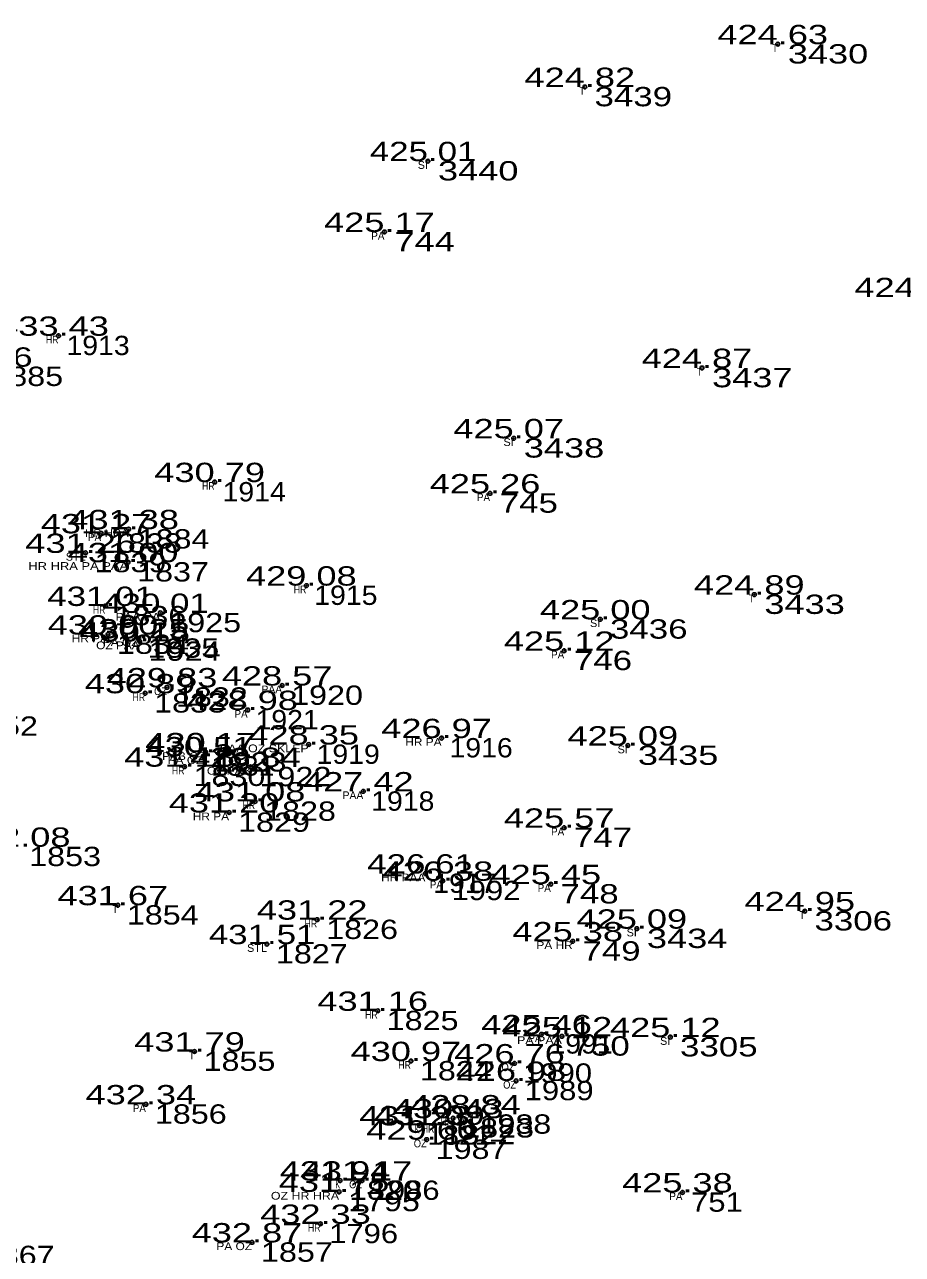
# Model space of a CAD drawing. Extents: x -639390 to -639074, y -1138747 to -1138358.
# Drawn here: x -639298.45 to -639264.37, y -1138517.05 to -1138469.3 of the extents above; entities that cross this region are included whole.
import ezdxf
from ezdxf.enums import TextEntityAlignment as Align

# ---------------------------------------------------------------- set-up
doc = ezdxf.new("R2010")
doc.units = 0
doc.header["$LTSCALE"] = 0.3
doc.header["$PDMODE"] = 32
doc.header["$PDSIZE"] = 0.15
for name, color, linetype in [('11', 7, 'Continuous'), ('12', 7, 'Continuous'), ('13', 7, 'Continuous'), ('57', 7, 'Continuous')]:
    doc.layers.add(name, color=color, linetype=linetype)

msp = doc.modelspace()

# ---------------------------------------------------------------- linework, layer by layer
at = {"layer": '11'}
for p in [(-639269.21, -1138470.06), (-639276.7, -1138471.72), (-639282.79, -1138474.6), (-639284.48, -1138477.35), (-639297.13, -1138481.38), (-639272.15, -1138482.63), (-639279.46, -1138485.36), (-639291.07, -1138487.06), (-639280.38, -1138487.5), (-639294.41, -1138488.89), (-639295.48, -1138489.05), (-639296.08, -1138489.81), (-639294.43, -1138490.17), (-639287.51, -1138491.08), (-639295.31, -1138491.87), (-639270.12, -1138491.43), (-639293.18, -1138492.14), (-639276.1, -1138492.39), (-639295.21, -1138492.98), (-639294.03, -1138493.13), (-639293.98, -1138493.25), (-639277.5, -1138493.61), (-639292.92, -1138495.03), (-639288.45, -1138494.96), (-639293.77, -1138495.26), (-639289.79, -1138495.91), (-639282.26, -1138497), (-639291.42, -1138497.55), (-639287.42, -1138497.25), (-639275.03, -1138497.29), (-639291.51, -1138497.71), (-639292.24, -1138498.11), (-639289.68, -1138498.12), (-639289.5, -1138499.46), (-639285.3, -1138499.07), (-639290.51, -1138499.89), (-639277.5, -1138500.48), (-639282.89, -1138502.26), (-639282.21, -1138502.54), (-639278.02, -1138502.67), (-639294.83, -1138503.49), (-639268.16, -1138503.72), (-639287.09, -1138504.05), (-639274.68, -1138504.4), (-639289.04, -1138505), (-639277.17, -1138504.89), (-639284.74, -1138507.59), (-639278.38, -1138508.5), (-639277.59, -1138508.58), (-639273.38, -1138508.61), (-639291.85, -1138509.17), (-639283.45, -1138509.54), (-639279.43, -1138509.63), (-639279.37, -1138510.31), (-639293.74, -1138511.22), (-639281.81, -1138511.76), (-639281.14, -1138511.61), (-639283.12, -1138512.04), (-639282.54, -1138512.02), (-639282.84, -1138512.59), (-639286.2, -1138514.18), (-639285.35, -1138514.18), (-639286.24, -1138514.62), (-639272.91, -1138514.64), (-639286.96, -1138515.86), (-639289.62, -1138516.58)]:
    msp.add_point(p, dxfattribs=at)

# ---------------------------------------------------------------- texts
at = {"layer": '12'}
for s, width, p in [('424.63 ', 1.4, (-639269.21, -1138470.06)), ('424.82 ', 1.4, (-639276.7, -1138471.72)), ('425.01 ', 1.35, (-639282.789, -1138474.6)), ('425.17 ', 1.4, (-639284.48, -1138477.35)), ('424.62 ', 1.4, (-639263.89, -1138479.88)), ('433.43 ', 1.4, (-639297.13, -1138481.38)), ('434.36 ', 1.4, (-639300.089, -1138482.58)), ('424.87 ', 1.4, (-639272.15, -1138482.63)), ('425.07 ', 1.4, (-639279.46, -1138485.36)), ('430.79 ', 1.4, (-639291.07, -1138487.06)), ('425.26 ', 1.4, (-639280.379, -1138487.5)), ('431.27 ', 1.4, (-639295.48, -1138489.05)), ('431.38 ', 1.4, (-639294.41, -1138488.89)), ('431.26 ', 1.4, (-639296.079, -1138489.81)), ('431.00 ', 1.4, (-639294.43, -1138490.17)), ('429.08 ', 1.4, (-639287.51, -1138491.08)), ('424.89 ', 1.4, (-639270.12, -1138491.43)), ('431.01 ', 1.35, (-639295.309, -1138491.87)), ('430.01 ', 1.35, (-639293.179, -1138492.14)), ('425.00 ', 1.4, (-639276.1, -1138492.39)), ('430.90 ', 1.4, (-639295.21, -1138492.98)), ('430.25 ', 1.4, (-639294.03, -1138493.13)), ('430.18 ', 1.4, (-639293.98, -1138493.25)), ('425.12 ', 1.4, (-639277.5, -1138493.61)), ('428.57 ', 1.4, (-639288.45, -1138494.96)), ('430.89 ', 1.4, (-639293.77, -1138495.26)), ('429.83 ', 1.4, (-639292.92, -1138495.03)), ('428.98 ', 1.4, (-639289.79, -1138495.91)), ('428.35 ', 1.4, (-639287.42, -1138497.25)), ('426.97 ', 1.4, (-639282.26, -1138497)), ('425.09 ', 1.4, (-639275.03, -1138497.29)), ('430.51 ', 1.35, (-639291.509, -1138497.71)), ('430.17 ', 1.4, (-639291.42, -1138497.55)), ('431.18 ', 1.4, (-639292.24, -1138498.11)), ('429.84 ', 1.4, (-639289.68, -1138498.12)), ('427.42 ', 1.4, (-639285.3, -1138499.07)), ('431.08 ', 1.4, (-639289.5, -1138499.46)), ('431.20 ', 1.4, (-639290.51, -1138499.89)), ('425.57 ', 1.4, (-639277.5, -1138500.48)), ('432.08 ', 1.4, (-639298.62, -1138501.22)), ('426.61 ', 1.35, (-639282.889, -1138502.26)), ('426.38 ', 1.4, (-639282.21, -1138502.54)), ('425.45 ', 1.4, (-639278.02, -1138502.67)), ('431.67 ', 1.4, (-639294.83, -1138503.49)), ('424.95 ', 1.4, (-639268.16, -1138503.72)), ('431.22 ', 1.4, (-639287.09, -1138504.05)), ('425.09 ', 1.4, (-639274.68, -1138504.4)), ('425.38 ', 1.4, (-639277.17, -1138504.89)), ('431.51 ', 1.35, (-639289.039, -1138505)), ('431.16 ', 1.4, (-639284.739, -1138507.59)), ('425.46 ', 1.4, (-639278.379, -1138508.5)), ('425.12 ', 1.4, (-639277.59, -1138508.58)), ('425.12 ', 1.4, (-639273.38, -1138508.61)), ('431.79 ', 1.4, (-639291.85, -1138509.17)), ('430.97 ', 1.4, (-639283.45, -1138509.54)), ('426.76 ', 1.4, (-639279.429, -1138509.63)), ('426.98 ', 1.4, (-639279.37, -1138510.31)), ('432.34 ', 1.4, (-639293.74, -1138511.22)), ('428.84 ', 1.4, (-639281.14, -1138511.61)), ('431.23 ', 1.4, (-639283.12, -1138512.04)), ('431.09 ', 1.4, (-639282.54, -1138512.02)), ('430.43 ', 1.4, (-639281.81, -1138511.76)), ('429.60 ', 1.4, (-639282.84, -1138512.59)), ('431.94 ', 1.4, (-639286.2, -1138514.18)), ('431.17 ', 1.4, (-639285.35, -1138514.18)), ('431.75 ', 1.4, (-639286.24, -1138514.62)), ('425.38 ', 1.4, (-639272.91, -1138514.64)), ('432.33 ', 1.4, (-639286.96, -1138515.86)), ('432.87 ', 1.4, (-639289.62, -1138516.58))]:
    msp.add_text(s, height=0.75, dxfattribs=dict(at, width=width)).set_placement(p, align=Align.CENTER)
at = {"layer": '13'}
for s, width, p in [(' 3430', 1.4, (-639269.21, -1138470.81)), (' 3439', 1.35, (-639276.7, -1138472.47)), (' 3440', 1.4, (-639282.79, -1138475.35)), (' 744', 1.4, (-639284.48, -1138478.1)), (' 1913', 1.1, (-639297.13, -1138482.13)), (' 1885', 1.25, (-639300.09, -1138483.33)), (' 3437', 1.4, (-639272.15, -1138483.38)), (' 3438', 1.4, (-639279.46, -1138486.11)), (' 1914', 1.1, (-639291.07, -1138487.81)), (' 745', 1.35, (-639280.38, -1138488.25)), (' 1884', 1.25, (-639294.41, -1138489.64)), (' 1838', 1.25, (-639295.48, -1138489.8)), (' 1839', 1.25, (-639296.08, -1138490.56)), (' 1837', 1.25, (-639294.43, -1138490.92)), (' 1915', 1.1, (-639287.51, -1138491.83)), (' 3433', 1.4, (-639270.12, -1138492.18)), (' 1836', 1.25, (-639295.31, -1138492.62)), (' 1925', 1.25, (-639293.18, -1138492.89)), (' 3436', 1.35, (-639276.1, -1138493.14)), (' 1834', 1.25, (-639295.21, -1138493.73)), (' 1835', 1.25, (-639294.03, -1138493.88)), (' 1924', 1.25, (-639293.98, -1138494)), (' 746', 1.35, (-639277.5, -1138494.36)), (' 1832', 1.25, (-639292.92, -1138495.78)), (' 1920', 1.25, (-639288.45, -1138495.71)), (' 1833', 1.25, (-639293.77, -1138496.01)), (' 1921', 1.1, (-639289.79, -1138496.66)), (' 1852', 1.25, (-639301.07, -1138496.91)), (' 1916', 1.1, (-639282.26, -1138497.75)), (' 1923', 1.25, (-639291.42, -1138498.3)), (' 1919', 1.1, (-639287.42, -1138498)), (' 3435', 1.4, (-639275.03, -1138498.04)), (' 1831', 1.1, (-639291.51, -1138498.46)), (' 1830', 1.25, (-639292.24, -1138498.86)), (' 1922', 1.25, (-639289.68, -1138498.87)), (' 1828', 1.25, (-639289.5, -1138500.21)), (' 1918', 1.1, (-639285.3, -1138499.82)), (' 1829', 1.25, (-639290.51, -1138500.64)), (' 747', 1.35, (-639277.5, -1138501.23)), (' 1853', 1.25, (-639298.62, -1138501.97)), (' 1917', 1.1, (-639282.89, -1138503.01)), (' 1992', 1.2, (-639282.21, -1138503.29)), (' 748', 1.35, (-639278.02, -1138503.42)), (' 1854', 1.25, (-639294.83, -1138504.24)), (' 3306', 1.35, (-639268.16, -1138504.47)), (' 1826', 1.25, (-639287.09, -1138504.8)), (' 3434', 1.4, (-639274.68, -1138505.15)), (' 1827', 1.25, (-639289.04, -1138505.75)), (' 749', 1.35, (-639277.17, -1138505.64)), (' 1825', 1.25, (-639284.74, -1138508.34)), (' 1991', 1.1, (-639278.38, -1138509.25)), (' 750', 1.35, (-639277.59, -1138509.33)), (' 3305', 1.35, (-639273.38, -1138509.36)), (' 1855', 1.25, (-639291.85, -1138509.92)), (' 1824', 1.25, (-639283.45, -1138510.29)), (' 1990', 1.2, (-639279.43, -1138510.38)), (' 1989', 1.2, (-639279.37, -1138511.06)), (' 1856', 1.25, (-639293.74, -1138511.97)), (' 1823', 1.25, (-639281.81, -1138512.51)), (' 1988', 1.25, (-639281.14, -1138512.36)), (' 1821', 1.1, (-639283.12, -1138512.79)), (' 1822', 1.25, (-639282.54, -1138512.77)), (' 1987', 1.25, (-639282.84, -1138513.34)), (' 1820', 1.25, (-639286.2, -1138514.93)), (' 1986', 1.2, (-639285.35, -1138514.93)), (' 1795', 1.25, (-639286.24, -1138515.37)), (' 751', 1.2, (-639272.91, -1138515.39)), (' 1796', 1.2, (-639286.96, -1138516.61)), (' 1857', 1.25, (-639289.62, -1138517.33)), (' 1867', 1.25, (-639300.42, -1138517.46))]:
    msp.add_text(s, height=0.75, dxfattribs=dict(at, width=width)).set_placement(p)
at = {"layer": '57'}
for s, width, p in [('T', 0.85, (-639269.21, -1138470.36)), ('T', 0.85, (-639276.7, -1138472.02)), ('SI', 1.05, (-639282.79, -1138474.9)), ('PA', 0.95, (-639284.48, -1138477.65)), ('HR', 0.85, (-639297.129, -1138481.68)), ('T', 0.85, (-639272.15, -1138482.93)), ('SI', 1.05, (-639279.46, -1138485.66)), ('HR', 0.85, (-639291.069, -1138487.36)), ('PA', 0.95, (-639280.38, -1138487.8)), ('HR HRA', 1.1, (-639294.41, -1138489.19)), ('PA', 0.95, (-639295.48, -1138489.35)), ('STL', 1.05, (-639296.079, -1138490.11)), ('HR HRA PA PAA', 1.25, (-639294.43, -1138490.47)), ('HR', 0.85, (-639287.509, -1138491.38)), ('T', 0.85, (-639270.12, -1138491.73)), ('HR', 0.85, (-639295.309, -1138492.17)), ('PAA PA', 1.2, (-639293.18, -1138492.44)), ('SI', 1.05, (-639276.1, -1138492.69)), ('HR PA', 1.15, (-639295.21, -1138493.28)), ('OZ PAA', 1.15, (-639293.98, -1138493.55)), ('PA OZ', 1.15, (-639294.029, -1138493.43)), ('PA', 0.95, (-639277.5, -1138493.91)), ('OZ', 0.9, (-639292.919, -1138495.33)), ('HR', 0.85, (-639293.769, -1138495.56)), ('PA', 0.95, (-639289.79, -1138496.21)), ('HR PA', 1.15, (-639282.26, -1138497.3)), ('PAB OZ', 1.15, (-639291.419, -1138497.85)), ('PAA OZ SKLEP', 1.2, (-639287.419, -1138497.55)), ('SI', 1.05, (-639275.03, -1138497.59)), ('PA OZ', 1.15, (-639291.509, -1138498.01)), ('HR', 0.85, (-639292.239, -1138498.41)), ('OZ PAB', 1.15, (-639289.679, -1138498.42)), ('HR PA', 1.15, (-639290.51, -1138500.19)), ('HR', 0.85, (-639289.499, -1138499.76)), ('PA', 0.95, (-639277.5, -1138500.78)), ('HR PAA', 1.15, (-639282.89, -1138502.56)), ('PA', 0.95, (-639282.21, -1138502.84)), ('PA', 0.95, (-639278.02, -1138502.97)), ('T', 0.85, (-639294.83, -1138503.79)), ('T', 0.85, (-639268.16, -1138504.02)), ('HR', 0.85, (-639287.089, -1138504.35)), ('SI', 1.05, (-639274.68, -1138504.7)), ('STL', 1.05, (-639289.039, -1138505.3)), ('PA HR', 1.15, (-639277.169, -1138505.19)), ('HR', 0.85, (-639284.739, -1138507.89)), ('PA', 0.95, (-639278.38, -1138508.8)), ('PA PAA', 1.2, (-639277.59, -1138508.88)), ('SI', 1.05, (-639273.38, -1138508.91)), ('T', 0.85, (-639291.85, -1138509.47)), ('HR', 0.85, (-639283.449, -1138509.84)), ('OZ', 0.9, (-639279.429, -1138509.93)), ('OZ', 0.9, (-639279.369, -1138510.61)), ('PA', 0.95, (-639293.74, -1138511.52)), ('HR', 0.85, (-639281.809, -1138512.06)), ('OZ', 0.9, (-639281.139, -1138511.91)), ('K', 0.65, (-639283.119, -1138512.34)), ('HR', 0.85, (-639282.539, -1138512.32)), ('OZ', 0.9, (-639282.839, -1138512.89)), ('K', 0.65, (-639286.199, -1138514.48)), ('OZ', 0.9, (-639285.349, -1138514.48)), ('OZ HR HRA', 1.2, (-639286.24, -1138514.92)), ('PA', 0.95, (-639272.91, -1138514.94)), ('HR', 0.85, (-639286.959, -1138516.16)), ('PA OZ', 1.15, (-639289.619, -1138516.88))]:
    msp.add_text(s, height=0.3, dxfattribs=dict(at, width=width)).set_placement(p, align=Align.RIGHT)
for p in [(-639288.45, -1138495.26), (-639285.3, -1138499.37)]:
    msp.add_text('PAA', height=0.3, dxfattribs=at).set_placement(p, align=Align.RIGHT)

doc.saveas('drawing.dxf')
